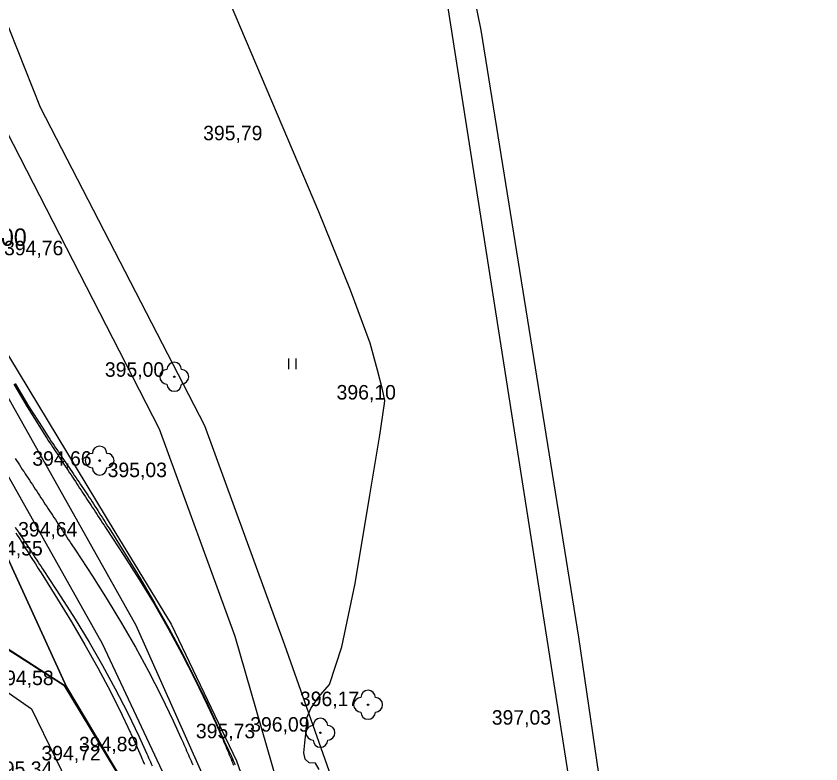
# Model space of a CAD drawing. Extents: x -574342 to -507939, y -1144044 to -1123894.
# Drawn here: x -508466.8 to -508411.2, y -1143168.4 to -1143116.7 of the extents above; entities that cross this region are included whole.
import ezdxf

# ---------------------------------------------------------------- set-up
doc = ezdxf.new("R2010")
doc.units = 0
for name, color, linetype in [('01_PARCELY_NAVRH_PC', 7, 'Continuous'), ('01_PARCELY_NAVRH_VHO', 7, 'Continuous'), ('01_PARCELY_NAVRH_ŽP', 7, 'Continuous'), ('1000', 7, 'Continuous'), ('15', 7, 'Continuous'), ('21', 7, 'Continuous'), ('37', 7, 'Continuous'), ('42', 7, 'Continuous'), ('43', 7, 'Continuous'), ('54', 7, 'Continuous'), ('55', 7, 'Continuous'), ('60', 7, 'Continuous'), ('Level 255', 7, 'Continuous'), ('VRST VEDL', 7, 'Continuous')]:
    doc.layers.add(name, color=color, linetype=linetype)

msp = doc.modelspace()

# ---------------------------------------------------------------- linework, layer by layer
at = {"layer": '01_PARCELY_NAVRH_PC'}
msp.add_lwpolyline([(-508426.41, -1143265.09), (-508431, -1143245.85), (-508431.86, -1143242.81), (-508432.73, -1143240.34), (-508445.99, -1143206.42), (-508454.33, -1143183.49), (-508456.87, -1143173.84), (-508463.3, -1143163.03), (-508476.26, -1143134.7), (-508479.46, -1143126.74), (-508474.05, -1143124.14), (-508467.92, -1143139.18), (-508459.97, -1143152.33), (-508456.09, -1143158.71), (-508451.57, -1143168.14), (-508437.66, -1143207.58), (-508425.52, -1143241.92), (-508422.7, -1143249.88), (-508420.08, -1143265.35)], dxfattribs=at)
at = {"layer": '01_PARCELY_NAVRH_VHO'}
msp.add_lwpolyline([(-508471.45, -1143157.79), (-508463.3, -1143163.03), (-508456.87, -1143173.84), (-508454.33, -1143183.49), (-508452.72, -1143198.2), (-508452.8, -1143209.75), (-508450.69, -1143221.56), (-508452.04, -1143229.57), (-508453.14, -1143234.1), (-508455.43, -1143236.54), (-508452.58, -1143244.39), (-508461.87, -1143244.49), (-508467.98, -1143243.62)], dxfattribs=at)
at = {"layer": '01_PARCELY_NAVRH_ŽP'}
msp.add_lwpolyline([(-508540.355, -1142847.7), (-508503.94, -1143018.7), (-508499.26, -1143041.98), (-508491.15, -1143065.29), (-508474.05, -1143124.14), (-508467.92, -1143139.18), (-508459.97, -1143152.33), (-508456.09, -1143158.71), (-508451.57, -1143168.14), (-508437.66, -1143207.58), (-508425.52, -1143241.92), (-508422.7, -1143249.88), (-508420.04, -1143252.1), (-508417.38, -1143252.95), (-508415.56, -1143252.78), (-508448.24, -1143160.16), (-508453.75, -1143145.01), (-508465.11, -1143123.03), (-508471.48, -1143106.99), (-508484.55, -1143061.98), (-508495.62, -1143031.06), (-508523.23, -1142904.28), (-508534.61, -1142847.7)], dxfattribs=at)
for points in [[(-508415.56, -1143252.78), (-508448.24, -1143160.16), (-508453.75, -1143145.01), (-508465.11, -1143123.03), (-508471.48, -1143106.99), (-508484.55, -1143061.98), (-508446.15, -1143057.71)], [(-508521.06, -1143176.58), (-508518.2, -1143171.1), (-508515.68, -1143172.08), (-508512.27, -1143171.56), (-508509.12, -1143169.33), (-508497.89, -1143158.09), (-508486.83, -1143153.3), (-508481.34, -1143149.03), (-508479.12, -1143143.52), (-508479.68, -1143136.88), (-508476.26, -1143134.7), (-508463.3, -1143163.03), (-508471.45, -1143157.79), (-508480.5, -1143156.13), (-508491.25, -1143159.19), (-508499.36, -1143164.43), (-508507.52, -1143173.92), (-508509.38, -1143179.27), (-508513.26, -1143177.6)]]:
    msp.add_lwpolyline(points, close=True, dxfattribs=at)
at = {"layer": '1000'}
for points in [[(-508466.938, -1143142.136), (-508466.015, -1143143.703), (-508465.056, -1143145.247), (-508464.754, -1143145.717), (-508464.659, -1143145.864), (-508464.563, -1143146.01), (-508464.468, -1143146.156), (-508464.371, -1143146.302), (-508464.275, -1143146.448), (-508464.178, -1143146.593), (-508464.081, -1143146.739), (-508464.061, -1143146.768), (-508464.061, -1143146.769), (-508463.982, -1143146.888), (-508463.883, -1143147.039), (-508463.784, -1143147.191), (-508463.685, -1143147.342), (-508463.586, -1143147.493), (-508463.487, -1143147.644), (-508463.388, -1143147.795), (-508463.289, -1143147.946), (-508463.19, -1143148.097), (-508463.09, -1143148.248), (-508462.991, -1143148.399), (-508462.892, -1143148.55), (-508462.793, -1143148.701), (-508462.694, -1143148.852), (-508462.595, -1143149.003), (-508462.496, -1143149.154), (-508462.397, -1143149.305), (-508462.298, -1143149.456), (-508462.199, -1143149.607), (-508462.1, -1143149.758), (-508462.001, -1143149.909), (-508461.901, -1143150.06), (-508461.802, -1143150.211), (-508461.703, -1143150.362), (-508461.604, -1143150.513), (-508461.505, -1143150.664), (-508461.406, -1143150.815), (-508461.307, -1143150.966), (-508461.208, -1143151.117), (-508461.109, -1143151.268), (-508461.01, -1143151.419), (-508460.911, -1143151.57), (-508460.812, -1143151.722), (-508460.712, -1143151.873), (-508460.613, -1143152.024), (-508460.514, -1143152.175), (-508459.342, -1143153.961), (-508458.282, -1143155.62), (-508457.262, -1143157.304), (-508456.282, -1143159.012), (-508455.342, -1143160.742), (-508454.445, -1143162.495), (-508453.589, -1143164.268), (-508453.01, -1143165.535), (-508452.945, -1143165.679), (-508452.881, -1143165.823), (-508452.817, -1143165.968), (-508452.776, -1143166.061), (-508452.754, -1143166.113), (-508452.69, -1143166.258), (-508452.627, -1143166.403), (-508452.565, -1143166.548), (-508452.502, -1143166.693), (-508452.44, -1143166.839), (-508452.378, -1143166.984), (-508452.316, -1143167.13), (-508452.255, -1143167.275), (-508452.194, -1143167.421), (-508452.133, -1143167.567), (-508452.072, -1143167.713), (-508452.012, -1143167.859), (-508452.006, -1143167.873), (-508451.952, -1143168.006), (-508451.892, -1143168.152), (-508451.833, -1143168.299), (-508451.815, -1143168.343), (-508451.774, -1143168.445)], [(-508466.856, -1143142.09), (-508465.92, -1143143.646), (-508464.948, -1143145.18), (-508464.643, -1143145.647), (-508464.547, -1143145.792), (-508464.45, -1143145.937), (-508464.353, -1143146.082), (-508464.255, -1143146.227), (-508464.157, -1143146.371), (-508464.059, -1143146.516), (-508463.96, -1143146.66), (-508463.94, -1143146.689), (-508463.94, -1143146.689), (-508463.86, -1143146.808), (-508463.759, -1143146.958), (-508463.658, -1143147.108), (-508463.556, -1143147.257), (-508463.455, -1143147.407), (-508463.354, -1143147.556), (-508463.252, -1143147.706), (-508463.151, -1143147.855), (-508463.049, -1143148.005), (-508462.948, -1143148.154), (-508462.847, -1143148.304), (-508462.746, -1143148.454), (-508462.645, -1143148.603), (-508462.543, -1143148.753), (-508462.442, -1143148.902), (-508462.34, -1143149.052), (-508462.239, -1143149.201), (-508462.137, -1143149.35), (-508462.035, -1143149.5), (-508461.933, -1143149.649), (-508461.834, -1143149.8), (-508461.734, -1143149.951), (-508461.635, -1143150.101), (-508461.536, -1143150.252), (-508461.436, -1143150.403), (-508461.339, -1143150.555), (-508461.242, -1143150.708), (-508461.146, -1143150.861), (-508461.049, -1143151.013), (-508460.952, -1143151.166), (-508460.855, -1143151.318), (-508460.758, -1143151.47), (-508460.661, -1143151.623), (-508460.564, -1143151.775), (-508460.467, -1143151.928), (-508460.371, -1143152.08), (-508459.228, -1143153.886), (-508458.193, -1143155.565), (-508457.198, -1143157.266), (-508456.241, -1143158.989), (-508455.309, -1143160.725), (-508454.415, -1143162.48), (-508453.559, -1143164.254), (-508452.977, -1143165.52), (-508452.912, -1143165.664), (-508452.847, -1143165.808), (-508452.783, -1143165.953), (-508452.741, -1143166.046), (-508452.718, -1143166.097), (-508452.654, -1143166.242), (-508452.59, -1143166.386), (-508452.526, -1143166.531), (-508452.462, -1143166.676), (-508452.398, -1143166.821), (-508452.332, -1143166.965), (-508452.264, -1143167.108), (-508452.196, -1143167.251), (-508452.128, -1143167.394), (-508452.061, -1143167.537), (-508451.993, -1143167.68), (-508451.926, -1143167.824), (-508451.919, -1143167.837), (-508451.858, -1143167.967), (-508451.794, -1143168.112), (-508451.737, -1143168.26), (-508451.72, -1143168.305), (-508451.68, -1143168.408)], [(-508466.844, -1143152.006), (-508466.745, -1143152.157), (-508466.646, -1143152.308), (-508466.547, -1143152.459), (-508466.448, -1143152.61), (-508466.348, -1143152.761), (-508466.249, -1143152.913), (-508466.15, -1143153.064), (-508466.051, -1143153.215), (-508465.952, -1143153.366), (-508465.853, -1143153.517), (-508465.754, -1143153.668), (-508465.655, -1143153.819), (-508465.556, -1143153.97), (-508465.457, -1143154.121), (-508465.358, -1143154.272), (-508465.259, -1143154.423), (-508465.159, -1143154.574), (-508465.06, -1143154.725), (-508464.961, -1143154.876), (-508464.862, -1143155.027), (-508463.69, -1143156.813), (-508462.697, -1143158.368), (-508461.74, -1143159.946), (-508460.822, -1143161.546), (-508459.942, -1143163.168), (-508459.101, -1143164.81), (-508458.299, -1143166.471), (-508457.756, -1143167.658), (-508457.696, -1143167.794), (-508457.636, -1143167.929), (-508457.576, -1143168.065), (-508457.538, -1143168.152), (-508457.516, -1143168.2), (-508457.457, -1143168.336), (-508457.398, -1143168.472)], [(-508466.795, -1143152.406), (-508466.699, -1143152.559), (-508466.603, -1143152.712), (-508466.507, -1143152.865), (-508466.411, -1143153.019), (-508466.316, -1143153.172), (-508466.22, -1143153.325), (-508466.125, -1143153.479), (-508466.029, -1143153.632), (-508465.934, -1143153.786), (-508465.839, -1143153.939), (-508465.744, -1143154.093), (-508465.649, -1143154.247), (-508465.548, -1143154.397), (-508465.447, -1143154.547), (-508465.351, -1143154.7), (-508465.256, -1143154.853), (-508465.16, -1143155.007), (-508465.065, -1143155.16), (-508463.936, -1143156.975), (-508462.971, -1143158.539), (-508462.033, -1143160.119), (-508461.133, -1143161.72), (-508460.274, -1143163.343), (-508459.455, -1143164.986), (-508458.678, -1143166.649), (-508458.16, -1143167.839), (-508458.101, -1143167.974), (-508458.042, -1143168.109), (-508457.983, -1143168.244), (-508457.945, -1143168.331), (-508457.924, -1143168.379)]]:
    msp.add_lwpolyline(points, dxfattribs=at)
at = {"layer": '21'}
msp.add_lwpolyline([(-508466.843, -1143147.253), (-508466.746, -1143147.405), (-508466.649, -1143147.557), (-508466.551, -1143147.709), (-508466.453, -1143147.861), (-508466.354, -1143148.012), (-508466.255, -1143148.164), (-508466.235, -1143148.194), (-508466.235, -1143148.195), (-508466.156, -1143148.315), (-508466.057, -1143148.466), (-508465.958, -1143148.617), (-508465.859, -1143148.768), (-508465.76, -1143148.919), (-508465.661, -1143149.07), (-508465.562, -1143149.221), (-508465.463, -1143149.372), (-508465.364, -1143149.523), (-508465.264, -1143149.674), (-508465.165, -1143149.825), (-508465.066, -1143149.976), (-508464.967, -1143150.127), (-508464.868, -1143150.278), (-508464.769, -1143150.429), (-508464.67, -1143150.58), (-508464.571, -1143150.731), (-508464.472, -1143150.882), (-508464.373, -1143151.033), (-508464.274, -1143151.184), (-508464.175, -1143151.335), (-508464.075, -1143151.486), (-508463.976, -1143151.637), (-508463.877, -1143151.788), (-508463.778, -1143151.939), (-508463.679, -1143152.09), (-508463.58, -1143152.242), (-508463.481, -1143152.393), (-508463.382, -1143152.544), (-508463.283, -1143152.695), (-508463.184, -1143152.846), (-508463.085, -1143152.997), (-508462.986, -1143153.148), (-508462.886, -1143153.299), (-508462.787, -1143153.45), (-508462.688, -1143153.601), (-508461.516, -1143155.387), (-508460.489, -1143156.994), (-508459.501, -1143158.625), (-508458.552, -1143160.279), (-508457.642, -1143161.955), (-508456.773, -1143163.652), (-508455.944, -1143165.37), (-508455.383, -1143166.596), (-508455.321, -1143166.736), (-508455.259, -1143166.876), (-508455.197, -1143167.016), (-508455.157, -1143167.106), (-508455.135, -1143167.157), (-508455.074, -1143167.297), (-508455.013, -1143167.437), (-508454.952, -1143167.578), (-508454.891, -1143167.719), (-508454.831, -1143167.859), (-508454.771, -1143168), (-508454.711, -1143168.141), (-508454.652, -1143168.282), (-508454.593, -1143168.424)], dxfattribs=at)
at = {"layer": '37'}
for points in [[(-508473.82, -1143129.8), (-508468.34, -1143141.31), (-508458.53, -1143158.76), (-508453.13, -1143170.86), (-508439.96, -1143210.5), (-508427.56, -1143241.73), (-508421.57, -1143265.72), (-508416.35, -1143292.6), (-508412.42, -1143304.7), (-508408.82, -1143311.83)], [(-508473.82, -1143129.8), (-508468.34, -1143141.31), (-508458.53, -1143158.76), (-508453.13, -1143170.86), (-508439.96, -1143210.5), (-508427.56, -1143241.73), (-508421.57, -1143265.72), (-508416.35, -1143292.6), (-508412.42, -1143304.7), (-508408.82, -1143311.83)], [(-508408.82, -1143311.83), (-508404.37, -1143317.04), (-508398.21, -1143321.18), (-508393.66, -1143322.44), (-508393.79, -1143324.58), (-508400.56, -1143323.11), (-508406.32, -1143319.06), (-508411.41, -1143313.16), (-508415.31, -1143305.9), (-508419.33, -1143292.88), (-508424.96, -1143264.72), (-508428.49, -1143248.11), (-508430.27, -1143242.09), (-508442.28, -1143211.48), (-508455.59, -1143171.17), (-508460.82, -1143160.05), (-508470.5, -1143142.85)], [(-508408.82, -1143311.83), (-508404.37, -1143317.04), (-508398.21, -1143321.18), (-508393.66, -1143322.44), (-508393.79, -1143324.58), (-508400.56, -1143323.11), (-508406.32, -1143319.06), (-508411.41, -1143313.16), (-508415.31, -1143305.9), (-508419.33, -1143292.88), (-508424.96, -1143264.72), (-508428.49, -1143248.11), (-508430.27, -1143242.09), (-508442.28, -1143211.48), (-508455.59, -1143171.17), (-508460.82, -1143160.05), (-508470.5, -1143142.85)]]:
    msp.add_lwpolyline(points, dxfattribs=at)
at = {"layer": '42'}
msp.add_lwpolyline([(-508320.88, -1143423.96), (-508327.62, -1143411.06), (-508338.78, -1143387.2), (-508344.67, -1143370.01), (-508350.79, -1143346.58), (-508354.96, -1143336.71), (-508361.36, -1143329.02), (-508368.91, -1143322.84), (-508376.72, -1143318.72), (-508388.31, -1143315.9), (-508393.87, -1143311.09), (-508396.73, -1143306.67), (-508407.7, -1143271.35), (-508414.18, -1143248.41), (-508420.68, -1143216.75), (-508423.64, -1143189.02), (-508427.95, -1143159.6), (-508434.68, -1143117.69), (-508439.72, -1143092.94), (-508444.13, -1143060.48), (-508445.89, -1143059.01)], dxfattribs=at)
msp.add_lwpolyline([(-508320.88, -1143423.96), (-508327.62, -1143411.06), (-508338.78, -1143387.2), (-508344.67, -1143370.01), (-508350.79, -1143346.58), (-508354.96, -1143336.71), (-508361.36, -1143329.02), (-508368.91, -1143322.84), (-508376.72, -1143318.72), (-508388.31, -1143315.9), (-508393.87, -1143311.09), (-508396.73, -1143306.67), (-508407.7, -1143271.35), (-508414.18, -1143248.41), (-508420.68, -1143216.75), (-508423.64, -1143189.02), (-508427.95, -1143159.6), (-508434.68, -1143117.69), (-508439.72, -1143092.94), (-508444.13, -1143060.48), (-508445.89, -1143059.01)], dxfattribs=at)
at = {"layer": '43'}
for p, q in [((-508447.951, -1143141.106), (-508447.951, -1143140.356)), ((-508447.451, -1143141.106), (-508447.451, -1143140.356))]:
    msp.add_line(p, q, dxfattribs=at)
at = {"layer": '54'}
for centre in [(-508455.87, -1143141.62), (-508461.02, -1143147.41), (-508442.49, -1143164.27), (-508445.78, -1143166.2)]:
    msp.add_circle(centre, 0.05, dxfattribs=at)
for centre, start, end in [((-508455.87, -1143141.12), 0, 180), ((-508456.37, -1143141.62), 90, 270), ((-508455.37, -1143141.62), 270, 90), ((-508455.87, -1143142.12), 180, 0), ((-508461.02, -1143146.91), 0, 180), ((-508461.52, -1143147.41), 90, 270), ((-508460.52, -1143147.41), 270, 90), ((-508461.02, -1143147.91), 180, 0), ((-508442.49, -1143163.77), 0, 180), ((-508442.99, -1143164.27), 90, 270), ((-508441.99, -1143164.27), 270, 90), ((-508442.49, -1143164.77), 180, 0), ((-508445.78, -1143165.7), 0, 180), ((-508446.28, -1143166.2), 90, 270), ((-508445.28, -1143166.2), 270, 90), ((-508445.78, -1143166.7), 180, 0)]:
    msp.add_arc(centre, 0.5, start, end, dxfattribs=at)
at = {"layer": '55'}
msp.add_lwpolyline([(-508486.89, -1143065.21), (-508480.57, -1143088.37), (-508477.81, -1143095.89), (-508475.78, -1143103.63), (-508468.39, -1143122.87), (-508456.91, -1143145.22), (-508451.68, -1143159.54), (-508438.58, -1143205.02)], dxfattribs=at)
msp.add_lwpolyline([(-508486.89, -1143065.21), (-508480.57, -1143088.37), (-508477.81, -1143095.89), (-508475.78, -1143103.63), (-508468.39, -1143122.87), (-508456.91, -1143145.22), (-508451.68, -1143159.54), (-508438.58, -1143205.02)], dxfattribs=at)
at = {"layer": '60'}
for points in [[(-508509.56, -1143179.75), (-508507.59, -1143174.03), (-508499.59, -1143164.63), (-508491.49, -1143159.34), (-508480.74, -1143156.18), (-508471.54, -1143157.78), (-508463.5, -1143162.91), (-508457.05, -1143173.57)], [(-508509.56, -1143179.75), (-508507.59, -1143174.03), (-508499.59, -1143164.63), (-508491.49, -1143159.34), (-508480.74, -1143156.18), (-508471.54, -1143157.78), (-508463.5, -1143162.91), (-508457.05, -1143173.57)], [(-508506.58, -1143184.83), (-508505.59, -1143179.84), (-508503.86, -1143175), (-508497.84, -1143167.31), (-508489.61, -1143162.43), (-508480.59, -1143159.39), (-508472.18, -1143160.07), (-508465.72, -1143164.54), (-508460.82, -1143174.63)], [(-508506.58, -1143184.83), (-508505.59, -1143179.84), (-508503.86, -1143175), (-508497.84, -1143167.31), (-508489.61, -1143162.43), (-508480.59, -1143159.39), (-508472.18, -1143160.07), (-508465.72, -1143164.54), (-508460.82, -1143174.63)]]:
    msp.add_lwpolyline(points, dxfattribs=at)
at = {"layer": 'VRST VEDL'}
msp.add_lwpolyline([(-508445.879, -1143168.726), (-508446.115, -1143168.294), (-508446.564, -1143168.269), (-508446.837, -1143168.03), (-508446.934, -1143167.575), (-508446.856, -1143166.905), (-508446.792, -1143166.28), (-508446.743, -1143165.699), (-508446.709, -1143165.164), (-508446.433, -1143164.515), (-508445.913, -1143163.753), (-508445.151, -1143162.878), (-508444.306, -1143160.26), (-508443.378, -1143155.899), (-508442.367, -1143149.795), (-508441.691, -1143145.654), (-508441.349, -1143143.476), (-508441.341, -1143143.262), (-508441.505, -1143142.493), (-508441.839, -1143141.17), (-508442.345, -1143139.293), (-508443.698, -1143135.648), (-508445.897, -1143130.235), (-508451.988, -1143115.875)], dxfattribs=at)

# ---------------------------------------------------------------- texts
at = {"layer": '15'}
msp.add_text('DN 200', height=1.2, dxfattribs=at).set_placement((-508471.489, -1143132.582))
msp.add_text('DN 200', height=1.2, dxfattribs=at).set_placement((-508471.489, -1143132.582))
at = {"layer": 'Level 255'}
for s, p in [('395,79', (-508453.875, -1143125.29)), ('394,76', (-508467.615, -1143133.23)), ('395,00', (-508460.655, -1143141.62)), ('396,10', (-508444.665, -1143143.19)), ('394,66', (-508465.665, -1143147.76)), ('395,03', (-508460.465, -1143148.55)), ('394,64', (-508466.645, -1143152.65)), ('394,55', (-508469.035, -1143153.96)), ('394,58', (-508468.285, -1143162.91)), ('396,17', (-508447.195, -1143164.36)), ('396,09', (-508450.625, -1143166.12)), ('397,03', (-508433.955, -1143165.64)), ('395,73', (-508454.375, -1143166.58)), ('394,89', (-508462.445, -1143167.48)), ('394,72', (-508465.035, -1143168.11)), ('395,34', (-508468.375, -1143169.18))]:
    msp.add_text(s, height=1, dxfattribs=at).set_placement(p)

doc.saveas('drawing.dxf')
